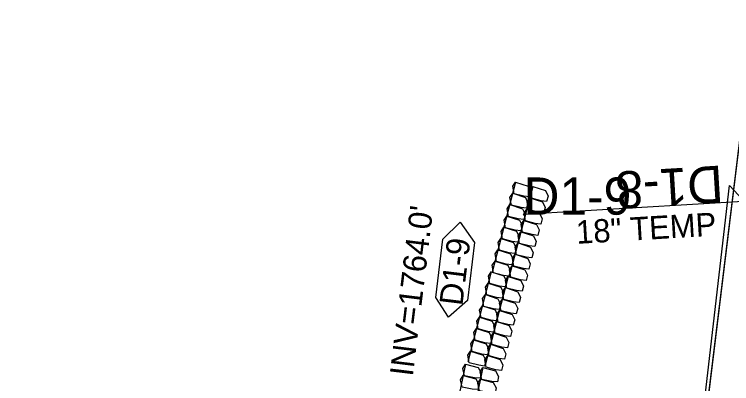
# Model space of a CAD drawing. Extents: x 465700 to 483515, y 488970 to 507540.
# Drawn here: x 481134.4 to 481288.8, y 490696.3 to 490775.7 of the extents above; entities that cross this region are included whole.
import ezdxf

# ---------------------------------------------------------------- set-up
doc = ezdxf.new("R2010")
doc.units = 0
for name, color, linetype in [('Exist Plan Preparation Watershed Blue', 7, 'Continuous'), ('Prop Drainage Structure Box Number Symbol CELL', 7, 'Continuous'), ('Prop Drainage Structure Outlet Generic CELL', 7, 'Continuous'), ('Prop Drainage Structure Pipe RCP 18in Class III', 7, 'Continuous'), ('Prop Drainage Structure Pipe RCP 18in Class III Label', 7, 'Continuous'), ('Prop Drainage Structure Tops and Inverts LABEL', 7, 'Continuous'), ('Prop Erosion Embankment Toe Protection CELL', 7, 'Continuous'), ('Scratch_Level_8', 7, 'Continuous')]:
    doc.layers.add(name, color=color, linetype=linetype)

msp = doc.modelspace()

# ---------------------------------------------------------------- linework, layer by layer
at = {"layer": 'Exist Plan Preparation Watershed Blue'}
for points in [[(481178.35, 489921.07), (481181.18, 489944.23), (481192.1, 489942.89), (481199.42, 490002.85), (481223.67, 490201.37), (481232.65, 490274.58), (481301.55, 490839.02), (481357.88, 490832.14), (481339.74, 490683.62), (481315.49, 490485.09), (481303.36, 490385.83), (481279.12, 490187.3), (481254.87, 489988.78), (481242.75, 489889.52)], [(480982.54, 490200.49), (481022.64, 490226.93), (481057.88, 490239.62), (481085.68, 490250.52), (481125.08, 490261.61), (481159, 490262.25), (481229.67, 490258.2), (481254.1, 490443.2), (481288.29, 490738.89), (481339.74, 490683.62), (481381.2, 490650.46), (481429.31, 490629.05), (481609.7, 490592.3), (481802.24, 490660.02), (481819.54, 490679.79), (481842.61, 490718.46), (481669.68, 490775.55), (481613.6, 490791.65)]]:
    msp.add_lwpolyline(points, dxfattribs=at)
msp.add_lwpolyline([(481259, 490360.8), (481243.71, 490365.51), (481284.29, 490697.69), (481301.55, 490839.02), (481323.3, 490836.37), (481281, 490489.23), (481265.22, 490360.1)], close=True, dxfattribs=at)
at = {"layer": 'Prop Drainage Structure Box Number Symbol CELL'}
msp.add_lwpolyline([(481225.11, 490714.83), (481226.64, 490727.34), (481230.35, 490731.02), (481233.42, 490726.67), (481231.89, 490714.16), (481227.86, 490710.62), (481225.11, 490714.83)], dxfattribs=at)
at = {"layer": 'Prop Drainage Structure Outlet Generic CELL'}
msp.add_line((481243.97, 490732.64), (481243.97, 490732.64), dxfattribs=at)
msp.add_line((481243.97, 490732.64), (481243.97, 490732.64), dxfattribs=at)
msp.add_circle((481243.97, 490732.64), 0.035, dxfattribs=at)
at = {"layer": 'Prop Drainage Structure Pipe RCP 18in Class III'}
msp.add_line((481330.8, 490737.8), (481243.97, 490732.64), dxfattribs=at)
at = {"layer": 'Prop Erosion Embankment Toe Protection CELL'}
for p, q in [((481242.28, 490739.65), (481237.24, 490720.3)), ((481245.96, 490738.69), (481240.92, 490719.34)), ((481237.02, 490720.31), (481231.98, 490700.96)), ((481240.7, 490719.35), (481235.66, 490700)), ((481231.47, 490700.49), (481227.46, 490680.9)), ((481235.19, 490699.73), (481231.18, 490680.14))]:
    msp.add_line(p, q, dxfattribs=at)
for points in [[(481245.27, 490736.44), (481244.07, 490736.6), (481241.99, 490737.14), (481241.69, 490738.77), (481242.28, 490739.65), (481245, 490738.79), (481245.57, 490737.58), (481245.27, 490736.44)], [(481248.95, 490735.49), (481247.75, 490735.64), (481245.67, 490736.19), (481245.37, 490737.81), (481245.96, 490738.69), (481248.68, 490737.83), (481249.25, 490736.62), (481248.95, 490735.49)], [(481244.64, 490734.03), (481243.44, 490734.16), (481241.36, 490734.7), (481241.06, 490736.35), (481241.65, 490737.23), (481244.37, 490736.34), (481244.93, 490735.14), (481244.64, 490734.03)], [(481248.32, 490733.07), (481247.11, 490733.2), (481245.03, 490733.74), (481244.74, 490735.39), (481245.33, 490736.27), (481248.05, 490735.39), (481248.61, 490734.18), (481248.32, 490733.07)], [(481244.01, 490731.58), (481242.8, 490731.72), (481240.72, 490732.26), (481240.43, 490733.91), (481241.02, 490734.79), (481243.73, 490733.9), (481244.3, 490732.72), (481244.01, 490731.58)], [(481247.68, 490730.62), (481246.48, 490730.76), (481244.4, 490731.3), (481244.1, 490732.95), (481244.69, 490733.83), (481247.41, 490732.94), (481247.98, 490731.76), (481247.68, 490730.62)], [(481243.37, 490729.14), (481242.17, 490729.3), (481240.09, 490729.84), (481239.79, 490731.47), (481240.38, 490732.35), (481243.1, 490731.48), (481243.67, 490730.3), (481243.37, 490729.14)], [(481247.05, 490728.18), (481245.85, 490728.34), (481243.77, 490728.88), (481243.47, 490730.51), (481244.06, 490731.39), (481246.78, 490730.52), (481247.35, 490729.34), (481247.05, 490728.18)], [(481242.74, 490726.72), (481241.54, 490726.88), (481239.46, 490727.42), (481239.16, 490729.05), (481239.75, 490729.93), (481242.47, 490729.06), (481243.03, 490727.86), (481242.74, 490726.72)], [(481246.42, 490725.76), (481245.22, 490725.92), (481243.14, 490726.46), (481242.84, 490728.09), (481243.43, 490728.97), (481246.15, 490728.1), (481246.71, 490726.9), (481246.42, 490725.76)], [(481242.11, 490724.3), (481240.9, 490724.43), (481238.82, 490724.98), (481238.53, 490726.63), (481239.12, 490727.51), (481241.83, 490726.62), (481242.4, 490725.41), (481242.11, 490724.3)], [(481245.78, 490723.34), (481244.58, 490723.48), (481242.5, 490724.02), (481242.21, 490725.67), (481242.8, 490726.55), (481245.51, 490725.66), (481246.07, 490724.45), (481245.78, 490723.34)], [(481241.47, 490721.86), (481240.27, 490721.99), (481238.19, 490722.53), (481237.89, 490724.18), (481238.48, 490725.06), (481241.2, 490724.18), (481241.77, 490722.99), (481241.47, 490721.86)], [(481245.15, 490720.9), (481243.94, 490721.03), (481241.86, 490721.57), (481241.57, 490723.23), (481242.16, 490724.11), (481244.87, 490723.22), (481245.44, 490722.04), (481245.15, 490720.9)], [(481240.83, 490719.41), (481239.64, 490719.57), (481237.55, 490720.11), (481237.26, 490721.74), (481237.85, 490722.62), (481240.57, 490721.76), (481241.14, 490720.57), (481240.83, 490719.41)], [(481240.01, 490717.11), (481238.81, 490717.26), (481236.73, 490717.81), (481236.43, 490719.43), (481237.02, 490720.31), (481239.74, 490719.45), (481240.31, 490718.24), (481240.01, 490717.11)], [(481244.51, 490718.46), (481243.31, 490718.61), (481241.23, 490719.16), (481240.93, 490720.78), (481241.52, 490721.66), (481244.24, 490720.8), (481244.81, 490719.62), (481244.51, 490718.46)], [(481243.69, 490716.15), (481242.49, 490716.31), (481240.41, 490716.85), (481240.11, 490718.48), (481240.7, 490719.35), (481243.42, 490718.49), (481243.98, 490717.28), (481243.69, 490716.15)], [(481239.38, 490714.69), (481238.17, 490714.82), (481236.09, 490715.36), (481235.8, 490717.01), (481236.39, 490717.89), (481239.11, 490717.01), (481239.67, 490715.8), (481239.38, 490714.69)], [(481243.06, 490713.73), (481241.85, 490713.86), (481239.77, 490714.4), (481239.48, 490716.06), (481240.07, 490716.94), (481242.78, 490716.05), (481243.35, 490714.84), (481243.06, 490713.73)], [(481238.74, 490712.24), (481237.54, 490712.38), (481235.46, 490712.92), (481235.16, 490714.57), (481235.76, 490715.45), (481238.47, 490714.56), (481239.04, 490713.38), (481238.74, 490712.24)], [(481242.42, 490711.29), (481241.22, 490711.42), (481239.13, 490711.96), (481238.84, 490713.61), (481239.43, 490714.49), (481242.15, 490713.6), (481242.72, 490712.42), (481242.42, 490711.29)], [(481238.11, 490709.8), (481236.91, 490709.96), (481234.83, 490710.5), (481234.53, 490712.13), (481235.12, 490713.01), (481237.84, 490712.14), (481238.41, 490710.96), (481238.11, 490709.8)], [(481241.78, 490708.84), (481240.58, 490709), (481238.5, 490709.54), (481238.2, 490711.17), (481238.8, 490712.05), (481241.52, 490711.19), (481242.09, 490710), (481241.78, 490708.84)], [(481237.48, 490707.38), (481236.28, 490707.54), (481234.2, 490708.08), (481233.9, 490709.71), (481234.49, 490710.59), (481237.21, 490709.72), (481237.77, 490708.52), (481237.48, 490707.38)], [(481241.15, 490706.42), (481239.95, 490706.58), (481237.87, 490707.12), (481237.57, 490708.75), (481238.17, 490709.63), (481240.89, 490708.77), (481241.45, 490707.56), (481241.15, 490706.42)], [(481236.85, 490704.96), (481235.64, 490705.1), (481233.56, 490705.64), (481233.27, 490707.29), (481233.86, 490708.17), (481236.57, 490707.28), (481237.14, 490706.07), (481236.85, 490704.96)], [(481240.52, 490704), (481239.32, 490704.14), (481237.24, 490704.68), (481236.94, 490706.33), (481237.53, 490707.21), (481240.25, 490706.32), (481240.81, 490705.12), (481240.52, 490704)], [(481236.21, 490702.52), (481235, 490702.65), (481232.92, 490703.19), (481232.63, 490704.85), (481233.22, 490705.73), (481235.93, 490704.84), (481236.51, 490703.66), (481236.21, 490702.52)], [(481239.89, 490701.56), (481238.68, 490701.69), (481236.6, 490702.24), (481236.31, 490703.89), (481236.9, 490704.77), (481239.61, 490703.88), (481240.18, 490702.7), (481239.89, 490701.56)], [(481235.57, 490700.08), (481234.37, 490700.23), (481232.29, 490700.77), (481231.99, 490702.4), (481232.58, 490703.28), (481235.3, 490702.42), (481235.87, 490701.24), (481235.57, 490700.08)], [(481239.25, 490699.12), (481238.05, 490699.27), (481235.97, 490699.82), (481235.67, 490701.44), (481236.26, 490702.32), (481238.98, 490701.46), (481239.55, 490700.28), (481239.25, 490699.12)], [(481234.62, 490697.45), (481233.42, 490697.54), (481231.31, 490697.97), (481230.92, 490699.58), (481231.47, 490700.49), (481234.23, 490699.78), (481234.86, 490698.6), (481234.62, 490697.45)], [(481238.35, 490696.69), (481237.14, 490696.78), (481235.03, 490697.21), (481234.65, 490698.82), (481235.19, 490699.73), (481237.95, 490699.02), (481238.58, 490697.84), (481238.35, 490696.69)], [(481234.12, 490695), (481232.91, 490695.07), (481230.8, 490695.5), (481230.42, 490697.14), (481230.97, 490698.04), (481233.72, 490697.3), (481234.35, 490696.13), (481234.12, 490695)], [(481237.84, 490694.24), (481236.63, 490694.31), (481234.53, 490694.74), (481234.15, 490696.37), (481234.69, 490697.28), (481237.45, 490696.54), (481238.07, 490695.37), (481237.84, 490694.24)]]:
    msp.add_lwpolyline(points, dxfattribs=at)
at = {"layer": 'Scratch_Level_8'}
msp.add_line((481330.37, 490737.85), (481243.97, 490732.64), dxfattribs=at)

# ---------------------------------------------------------------- texts
at = {"layer": 'Prop Drainage Structure Box Number Symbol CELL'}
msp.add_text('D1-9', height=5, rotation=83.0394, dxfattribs=at).set_placement((481230.81, 490712.9))
at = {"layer": 'Prop Drainage Structure Outlet Generic CELL'}
msp.add_text('O', height=0.05, rotation=343.0365, dxfattribs=at).set_placement((481243.95, 490732.62))
at = {"layer": 'Prop Drainage Structure Pipe RCP 18in Class III Label'}
msp.add_text('18" TEMP', height=5, rotation=3.4015, dxfattribs=at).set_placement((481255.41, 490726.35))
at = {"layer": 'Prop Drainage Structure Tops and Inverts LABEL'}
msp.add_text("INV=1764.0'", height=5, rotation=83.0394, dxfattribs=at).set_placement((481220.14, 490697.71))
at = {"layer": 'Scratch_Level_8'}
msp.add_text('D1-8', height=8, rotation=183.4511, dxfattribs=at).set_placement((481286.69, 490743.23))
msp.add_text('D1-9', height=8, dxfattribs=at).set_placement((481243.97, 490732.64))

doc.saveas('drawing.dxf')
